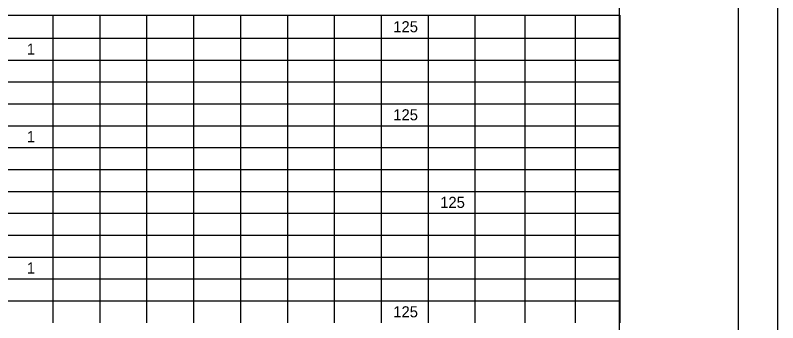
# Model space of a CAD drawing. Extents: x 0.2 to 34.2, y 0 to 22.
# Drawn here: x 24.55 to 34.19, y 6.64 to 10.52 of the extents above; entities that cross this region are included whole.
import ezdxf

# ---------------------------------------------------------------- set-up
doc = ezdxf.new("R2010")
doc.units = 0
for name, color, linetype in [('SH_Border', 7, 'Continuous'), ('SH_Cut_Line', 7, 'Continuous'), ('SH_Text', 7, 'Continuous')]:
    doc.layers.add(name, color=color, linetype=linetype)

msp = doc.modelspace()

# ---------------------------------------------------------------- linework, layer by layer
at = {"layer": 'SH_Border'}
msp.add_line((32.192, 0.5253), (32.192, 21.5253), dxfattribs=at)
msp.add_lwpolyline([(1.692, 21.5253), (33.692, 21.5253), (33.692, 0.5253), (1.692, 0.5253)], close=True, dxfattribs=at)
at = {"layer": 'SH_Cut_Line'}
msp.add_lwpolyline([(0.192, 0.0253), (34.192, 0.0253), (34.192, 22.0253), (0.192, 22.0253)], close=True, dxfattribs=at)
at = {"layer": 'SH_Text'}
for p, q in [((24.4346, 10.5229), (32.1955, 10.5229)), ((25.0275, 10.5229), (25.0275, 10.233)), ((25.6205, 10.5229), (25.6205, 10.233)), ((26.2134, 10.5229), (26.2134, 10.233)), ((26.8064, 10.5229), (26.8064, 10.233)), ((27.3993, 10.5229), (27.3993, 10.233)), ((27.9922, 10.5229), (27.9922, 10.233)), ((28.5852, 10.5229), (28.5852, 10.233)), ((29.1781, 10.5229), (29.1781, 10.233)), ((29.7711, 10.5229), (29.7711, 10.233)), ((30.364, 10.5229), (30.364, 10.233)), ((30.9965, 10.5229), (30.9965, 10.233)), ((31.629, 10.5229), (31.629, 10.233)), ((32.1955, 10.5229), (32.1955, 10.233)), ((24.4346, 10.233), (32.1955, 10.233)), ((25.0275, 10.233), (25.0275, 9.9563)), ((25.6205, 10.233), (25.6205, 9.9563)), ((26.2134, 10.233), (26.2134, 9.9563)), ((26.8064, 10.233), (26.8064, 9.9563)), ((27.3993, 10.233), (27.3993, 9.9563)), ((27.9922, 10.233), (27.9922, 9.9563)), ((28.5852, 10.233), (28.5852, 9.9563)), ((29.1781, 10.233), (29.1781, 9.9563)), ((29.7711, 10.233), (29.7711, 9.9563)), ((30.364, 10.233), (30.364, 9.9563)), ((30.9965, 10.233), (30.9965, 9.9563)), ((31.629, 10.233), (31.629, 9.9563)), ((32.1955, 10.233), (32.1955, 9.9563)), ((24.4346, 9.9563), (32.1955, 9.9563)), ((25.0275, 9.9563), (25.0275, 9.6796)), ((25.6205, 9.9563), (25.6205, 9.6796)), ((26.2134, 9.9563), (26.2134, 9.6796)), ((26.8064, 9.9563), (26.8064, 9.6796)), ((27.3993, 9.9563), (27.3993, 9.6796)), ((27.9922, 9.9563), (27.9922, 9.6796)), ((28.5852, 9.9563), (28.5852, 9.6796)), ((29.1781, 9.9563), (29.1781, 9.6796)), ((29.7711, 9.9563), (29.7711, 9.6796)), ((30.364, 9.9563), (30.364, 9.6796)), ((30.9965, 9.9563), (30.9965, 9.6796)), ((31.629, 9.9563), (31.629, 9.6796)), ((32.1955, 9.9563), (32.1955, 9.6796)), ((24.4346, 9.6796), (32.1955, 9.6796)), ((25.0275, 9.6796), (25.0275, 9.4029)), ((25.6205, 9.6796), (25.6205, 9.4029)), ((26.2134, 9.6796), (26.2134, 9.4029)), ((26.8064, 9.6796), (26.8064, 9.4029)), ((27.3993, 9.6796), (27.3993, 9.4029)), ((27.9922, 9.6796), (27.9922, 9.4029)), ((28.5852, 9.6796), (28.5852, 9.4029)), ((29.1781, 9.6796), (29.1781, 9.4029)), ((29.7711, 9.6796), (29.7711, 9.4029)), ((30.364, 9.6796), (30.364, 9.4029)), ((30.9965, 9.6796), (30.9965, 9.4029)), ((31.629, 9.6796), (31.629, 9.4029)), ((32.1955, 9.6796), (32.1955, 9.4029)), ((24.4346, 9.4029), (32.1955, 9.4029)), ((25.0275, 9.4029), (25.0275, 9.1262)), ((25.6205, 9.4029), (25.6205, 9.1262)), ((26.2134, 9.4029), (26.2134, 9.1262)), ((26.8064, 9.4029), (26.8064, 9.1262)), ((27.3993, 9.4029), (27.3993, 9.1262)), ((27.9922, 9.4029), (27.9922, 9.1262)), ((28.5852, 9.4029), (28.5852, 9.1262)), ((29.1781, 9.4029), (29.1781, 9.1262)), ((29.7711, 9.4029), (29.7711, 9.1262)), ((30.364, 9.4029), (30.364, 9.1262)), ((30.9965, 9.4029), (30.9965, 9.1262)), ((31.629, 9.4029), (31.629, 9.1262)), ((32.1955, 9.4029), (32.1955, 9.1262)), ((24.4346, 9.1262), (32.1955, 9.1262)), ((25.0275, 9.1262), (25.0275, 8.8495)), ((25.6205, 9.1262), (25.6205, 8.8495)), ((26.2134, 9.1262), (26.2134, 8.8495)), ((26.8064, 9.1262), (26.8064, 8.8495)), ((27.3993, 9.1262), (27.3993, 8.8495)), ((27.9922, 9.1262), (27.9922, 8.8495)), ((28.5852, 9.1262), (28.5852, 8.8495)), ((29.1781, 9.1262), (29.1781, 8.8495)), ((29.7711, 9.1262), (29.7711, 8.8495)), ((30.364, 9.1262), (30.364, 8.8495)), ((30.9965, 9.1262), (30.9965, 8.8495)), ((31.629, 9.1262), (31.629, 8.8495)), ((32.1955, 9.1262), (32.1955, 8.8495)), ((24.4346, 8.8495), (32.1955, 8.8495)), ((25.0275, 8.8495), (25.0275, 8.5728)), ((25.6205, 8.8495), (25.6205, 8.5728)), ((26.2134, 8.8495), (26.2134, 8.5728)), ((26.8064, 8.8495), (26.8064, 8.5728)), ((27.3993, 8.8495), (27.3993, 8.5728)), ((27.9922, 8.8495), (27.9922, 8.5728)), ((28.5852, 8.8495), (28.5852, 8.5728)), ((29.1781, 8.8495), (29.1781, 8.5728)), ((29.7711, 8.8495), (29.7711, 8.5728)), ((30.364, 8.8495), (30.364, 8.5728)), ((30.9965, 8.8495), (30.9965, 8.5728)), ((31.629, 8.8495), (31.629, 8.5728)), ((32.1955, 8.8495), (32.1955, 8.5728)), ((24.4346, 8.5728), (32.1955, 8.5728)), ((25.0275, 8.5728), (25.0275, 8.2961)), ((25.6205, 8.5728), (25.6205, 8.2961)), ((26.2134, 8.5728), (26.2134, 8.2961)), ((26.8064, 8.5728), (26.8064, 8.2961)), ((27.3993, 8.5728), (27.3993, 8.2961)), ((27.9922, 8.5728), (27.9922, 8.2961)), ((28.5852, 8.5728), (28.5852, 8.2961)), ((29.1781, 8.5728), (29.1781, 8.2961)), ((29.7711, 8.5728), (29.7711, 8.2961)), ((30.364, 8.5728), (30.364, 8.2961)), ((30.9965, 8.5728), (30.9965, 8.2961)), ((31.629, 8.5728), (31.629, 8.2961)), ((32.1955, 8.5728), (32.1955, 8.2961)), ((24.4346, 8.2961), (32.1955, 8.2961)), ((25.0275, 8.2961), (25.0275, 8.0194)), ((25.6205, 8.2961), (25.6205, 8.0194)), ((26.2134, 8.2961), (26.2134, 8.0194)), ((26.8064, 8.2961), (26.8064, 8.0194)), ((27.3993, 8.2961), (27.3993, 8.0194)), ((27.9922, 8.2961), (27.9922, 8.0194)), ((28.5852, 8.2961), (28.5852, 8.0194)), ((29.1781, 8.2961), (29.1781, 8.0194)), ((29.7711, 8.2961), (29.7711, 8.0194)), ((30.364, 8.2961), (30.364, 8.0194)), ((30.9965, 8.2961), (30.9965, 8.0194)), ((31.629, 8.2961), (31.629, 8.0194)), ((32.1955, 8.2961), (32.1955, 8.0194)), ((24.4346, 8.0194), (32.1955, 8.0194)), ((25.0275, 8.0194), (25.0275, 7.7427)), ((25.6205, 8.0194), (25.6205, 7.7427)), ((26.2134, 8.0194), (26.2134, 7.7427)), ((26.8064, 8.0194), (26.8064, 7.7427)), ((27.3993, 8.0194), (27.3993, 7.7427)), ((27.9922, 8.0194), (27.9922, 7.7427)), ((28.5852, 8.0194), (28.5852, 7.7427)), ((29.1781, 8.0194), (29.1781, 7.7427)), ((29.7711, 8.0194), (29.7711, 7.7427)), ((30.364, 8.0194), (30.364, 7.7427)), ((30.9965, 8.0194), (30.9965, 7.7427)), ((31.629, 8.0194), (31.629, 7.7427)), ((32.1955, 8.0194), (32.1955, 7.7427)), ((24.4346, 7.7427), (32.1955, 7.7427)), ((25.0275, 7.7427), (25.0275, 7.466)), ((25.6205, 7.7427), (25.6205, 7.466)), ((26.2134, 7.7427), (26.2134, 7.466)), ((26.8064, 7.7427), (26.8064, 7.466)), ((27.3993, 7.7427), (27.3993, 7.466)), ((27.9922, 7.7427), (27.9922, 7.466)), ((28.5852, 7.7427), (28.5852, 7.466)), ((29.1781, 7.7427), (29.1781, 7.466)), ((29.7711, 7.7427), (29.7711, 7.466)), ((30.364, 7.7427), (30.364, 7.466)), ((30.9965, 7.7427), (30.9965, 7.466)), ((31.629, 7.7427), (31.629, 7.466)), ((32.1955, 7.7427), (32.1955, 7.466)), ((24.4346, 7.466), (32.1955, 7.466)), ((25.0275, 7.466), (25.0275, 7.1893)), ((25.6205, 7.466), (25.6205, 7.1893)), ((26.2134, 7.466), (26.2134, 7.1893)), ((26.8064, 7.466), (26.8064, 7.1893)), ((27.3993, 7.466), (27.3993, 7.1893)), ((27.9922, 7.466), (27.9922, 7.1893)), ((28.5852, 7.466), (28.5852, 7.1893)), ((29.1781, 7.466), (29.1781, 7.1893)), ((29.7711, 7.466), (29.7711, 7.1893)), ((30.364, 7.466), (30.364, 7.1893)), ((30.9965, 7.466), (30.9965, 7.1893)), ((31.629, 7.466), (31.629, 7.1893)), ((32.1955, 7.466), (32.1955, 7.1893)), ((24.4346, 7.1893), (32.1955, 7.1893)), ((25.0275, 7.1893), (25.0275, 6.9126)), ((25.6205, 7.1893), (25.6205, 6.9126)), ((26.2134, 7.1893), (26.2134, 6.9126)), ((26.8064, 7.1893), (26.8064, 6.9126)), ((27.3993, 7.1893), (27.3993, 6.9126)), ((27.9922, 7.1893), (27.9922, 6.9126)), ((28.5852, 7.1893), (28.5852, 6.9126)), ((29.1781, 7.1893), (29.1781, 6.9126)), ((29.7711, 7.1893), (29.7711, 6.9126)), ((30.364, 7.1893), (30.364, 6.9126)), ((30.9965, 7.1893), (30.9965, 6.9126)), ((31.629, 7.1893), (31.629, 6.9126)), ((32.1955, 7.1893), (32.1955, 6.9126)), ((24.4346, 6.9126), (32.1955, 6.9126)), ((25.0275, 6.9126), (25.0275, 6.6359)), ((25.6205, 6.9126), (25.6205, 6.6359)), ((26.2134, 6.9126), (26.2134, 6.6359)), ((26.8064, 6.9126), (26.8064, 6.6359)), ((27.3993, 6.9126), (27.3993, 6.6359)), ((27.9922, 6.9126), (27.9922, 6.6359)), ((28.5852, 6.9126), (28.5852, 6.6359)), ((29.1781, 6.9126), (29.1781, 6.6359)), ((29.7711, 6.9126), (29.7711, 6.6359)), ((30.364, 6.9126), (30.364, 6.6359)), ((30.9965, 6.9126), (30.9965, 6.6359)), ((31.629, 6.9126), (31.629, 6.6359)), ((32.1955, 6.9126), (32.1955, 6.6359))]:
    msp.add_line(p, q, dxfattribs=at)

# ---------------------------------------------------------------- texts
for s, p in [('125', (29.3313, 10.308)), ('1', (24.6983, 10.0247)), ('125', (29.3313, 9.1946)), ('1', (24.6983, 8.9179)), ('125', (29.9243, 8.0877)), ('1', (24.6983, 7.2576)), ('125', (29.3313, 6.7042))]:
    msp.add_text(s, height=0.14, dxfattribs=at).set_placement(p)

doc.saveas('drawing.dxf')
